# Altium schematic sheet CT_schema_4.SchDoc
size 176 x 147 mm
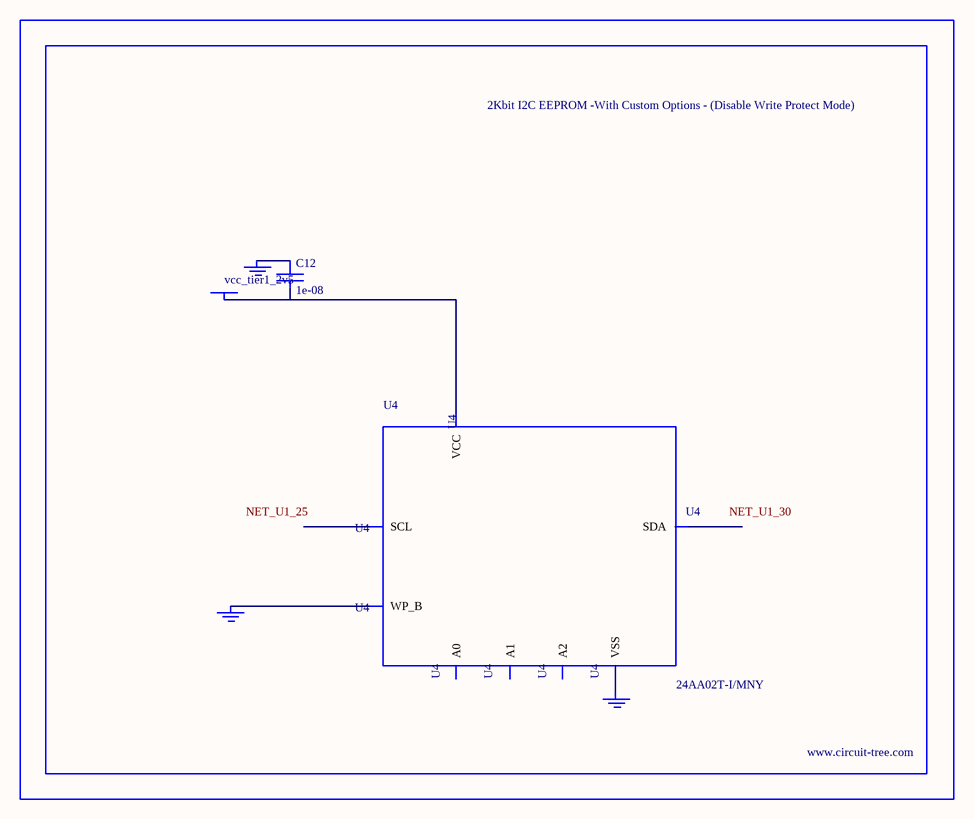
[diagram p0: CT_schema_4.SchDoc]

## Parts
BORDER3  (no value)
C12  1e-08  [C0402]
GND_INSTANCE_3_0  (no value)
GND_INSTANCE_3_1  (no value)
GND_INSTANCE_3_2  (no value)
POWER_INSTANCE_3_0  vcc_tier1_2v5
U4  24AA02T-I/MNY  [TDFN-8/6MM]

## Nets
NetC12_1: C12.1 GND_INSTANCE_3_1.0(GND)
NetC12_2: C12.2 POWER_INSTANCE_3_0.0(PWR) U4.8(VCC)
NetGND_INSTANCE_3_0_0: GND_INSTANCE_3_0.0(GND) U4.7(WP_B)
NetGND_INSTANCE_3_2_0: GND_INSTANCE_3_2.0(GND) U4.4(VSS)

Not connected (* = marked no-connect by the designer): U4 1(A0) 2(A1) 3(A2) 5(SDA) 6(SCL)

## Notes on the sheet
- Labels drawn without touching a wire or pin: NET_U1_25, NET_U1_30

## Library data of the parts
BORDER3 = BORDER_PAGE3
C12 = C0402C103K3RAC
GND_INSTANCE_3_0-GND_INSTANCE_3_2 = GND
POWER_INSTANCE_3_0 = PWR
